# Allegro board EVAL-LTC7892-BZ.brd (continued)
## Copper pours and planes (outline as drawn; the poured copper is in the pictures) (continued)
UNNAMED_2_ADLTC7892V2_I690_SW2 on LAYER_2: 64.52,49.78 64.39,49.78 64.39,49.4 60.83,49.4 59.56,50.67 59.56,55.88 57.66,55.88 57.66,49.66 59.82,47.5 64.31,47.5 64.31,46.94 64.52,46.94 ; 1 cut-out
UNNAMED_2_ADLTC7892V2_I690_SW2 on LAYER_3: 68.58,47.02 73.15,47.02 73.15,35.05 77.22,30.99 81.28,30.99 81.28,45.97 76.07,51.18 68.58,51.18
UNNAMED_2_ADLTC7892V2_I690_SW2 on LAYER_4: 69.22,46.91 73.28,46.91 73.28,34.92 77.22,30.99 81.28,30.99 81.28,46.35 76.2,51.43 69.22,51.43
UNNAMED_2_ADLTC7892V2_I690_TGDN1 on TOP (solid shape): 62.36,69.85 61.21,69.85 59.05,67.69 59.05,63.75 58.17,62.86 58.17,64.52 58.42,64.77 58.42,67.94 61.09,70.61 62.36,70.61
UNNAMED_2_ADLTC7892V2_I690_TGDN2 on TOP (solid shape): 58.47,55.09 58.47,54.18 59.56,53.09 59.56,50.67 60.83,49.4 62.48,49.4 62.48,48.64 60.45,48.64 58.86,50.23 58.86,52.64 58.17,53.34 58.17,55.24 58.32,55.24
UNNAMED_2_ADLTC7892V2_I690_TGUP1 on TOP (solid shape): 62.36,70.99 61.09,70.99 58.17,68.07 58.17,65.02 57.91,64.77 57.91,63.5 57.78,63.5 57.53,63.75 57.53,68.45 60.83,71.75 62.36,71.75
UNNAMED_2_ADLTC7892V2_I690_TGUP2 on TOP (solid shape): 58.42,52.45 58.42,50.04 60.2,48.26 62.48,48.26 62.48,47.5 59.82,47.5 57.66,49.66 57.66,53.21
UNNAMED_2_CAP_I211_N1 on BOTTOM: 54.48,69.22 54.48,64.9 55.88,64.9 55.88,69.22
UNNAMED_2_CAP_I552_N1 on TOP: 56.13,51.64 56.13,49.35 57.28,49.35 57.28,51.64
UNNAMED_2_CAP_I715_N1 on BOTTOM: 49.34,64.52 49.34,63.5 51.75,63.5 51.75,64.52
UNNAMED_2_CAP_I718_N1 on BOTTOM: 12.95,51.05 12.95,44.83 14.22,44.83 14.22,51.05
UNNAMED_2_CAP_I719_N1 on BOTTOM: 12.95,25.02 12.95,19.18 14.22,19.18 14.22,25.02
UNNAMED_2_CNBNC5P_I602_CNTR on TOP: 62.74,71.75 62.74,69.85 63.5,69.85 63.5,70.99 64.77,70.99 64.77,71.75
UNNAMED_2_CNBNC5P_I602_CNTR on BOTTOM: 62.74,72.01 62.74,70.99 64.77,70.99 64.77,72.01
UNNAMED_2_CNBNC5P_I603_CNTR on TOP: 62.74,49.4 64.64,49.4 64.64,48.64 63.83,48.64 63.5,48.31 63.5,47.5 62.74,47.5
UNNAMED_2_CNBNC5P_I603_CNTR on BOTTOM: 62.74,48.56 64.77,48.56 64.77,49.45 62.74,49.45
UNNAMED_2_IND_I545_N2 on BOTTOM: 62.74,83.19 66.67,83.19 66.67,91.57 61.98,96.27 54.1,96.27 54.1,89.41 61.59,89.41 62.74,88.27
UNNAMED_2_IND_I546_N1 on BOTTOM: 62.48,35.94 62.48,31.24 61.21,29.97 54.36,29.97 54.36,23.37 64.14,23.37 66.8,26.03 66.8,35.94
UNNAMED_2_RES_I628_N1 on TOP: 62.74,67.94 62.74,65.91 64.06,65.91 64.06,67.18 64.67,67.18 64.67,67.94
UNNAMED_2_RES_I641_N2 on TOP: 62.74,53.21 64.64,53.21 64.64,52.45 63.94,52.45 63.94,51.43 62.74,51.43
VFB1 on TOP: 54.48,70.74 54.48,65.02 55.75,65.02 55.75,70.74
VFB2 on TOP: 52.98,53.31 52.98,47.75 55.63,47.75 55.63,49 54.36,49 54.05,49.3 54.05,53.31
VOSP1 on TOP: 56.39,73.15 56.39,68.2 57.45,68.2 57.45,73.15
VOSP2 on TOP: 51.28,50.55 51.28,46.41 52.3,46.41 52.3,50.55
VOUT1 on TOP: 102.74,81.03 114.94,81.03 119.51,76.45 119.51,59.82 102.74,59.82
VOUT1 on TOP: 58.29,74.8 58.29,72.52 59.82,72.52 60.33,72.01 64.92,72.01 64.92,70.99 67.16,70.99 67.16,72.14 80.14,72.14 80.14,68.33 103.76,68.33 103.76,81.03 76.71,81.03 74.17,78.49 64.64,78.49 64.64,74.8
VOUT1 on BOTTOM: 101.6,81.79 111.12,81.79 116.71,76.2 116.71,59.82 101.6,59.82
VOUT1 on BOTTOM: 60.71,74.55 60.71,72.39 80.14,72.39 80.14,68.33 102.36,68.33 102.36,81.79 99.69,81.79 96.39,78.49 64.52,78.49 64.52,74.55
VOUT2 on TOP: 119.51,59.31 119.51,42.42 115.44,38.35 102.74,38.35 102.74,59.31
VOUT2 on TOP: 60.58,47.24 60.58,44.58 64.52,44.58 64.52,40.89 73.66,40.89 76.2,38.35 103.76,38.35 103.76,51.05 80.14,51.05 80.14,47.24 67.18,47.24 67.18,48.39 64.9,48.39 64.9,47.24
VOUT2 on BOTTOM: 60.58,47.24 60.58,44.58 64.52,44.58 64.52,40.89 95.89,40.89 99.31,37.46 102.23,37.46 102.23,51.05 80.14,51.05 80.14,47.24
VOUT2 on BOTTOM: 116.71,59.31 116.71,43.56 110.62,37.46 101.6,37.46 101.6,59.31

Small or netless copper shapes (teardrops, artwork), in the pictures only: 7 on BOTTOM, 4 on TOP

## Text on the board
User.Comments: 1 | 5.   INSTALL BANANA JACK  KEYSTONE 575-4 AS SHOWN BELOW. | 6.    INSTALL STUD HARDWARE SET AS SHOWN BELOW: | BOTTOME SIDE | TOP SIDE | * RING LUG FACE TO THE EDGE OF THE BOARD. | SOLDER | PCB | * | NUT,BRASS,#10-32 | (PRESS FIT AND SOLDER THIS SIDE) | STUD, PRESS FIT | WASHER, LOCK #10 | LUG, RING, #10
Ref Des/Assembly Top: P3, P4.  INSTALL SHUNTS ACROSS PIN1 AND PIN2 | P1.  INSTALL SHUNT ACROSS PIN5 AND PIN6 | P2.  INSTALL SHUNT ACROSS PIN3 AND PIN4
Ref Des/Silkscreen Top: * | mm | 10 | PLLIN/SPREAD | MODE | RUN1 | RUN2 | FC MODE | PULSE SKIP | BURST MODE | ENABLE SSFM | EXTERNAL SYNC | DISABLE SSFM | FOR MAXIMUM POWER | SEE USER GUIDE | 1.2kW Max | ON | OFF | SYNC | PGOOD1 | SS1 | SS2 | VIN | PGOOD2 | DUAL OUTPUT, 2-PHASE, 100V BOOST | CONTROLLER FOR GaN FETS | EXTVCC | GND | VOSP2 | VOSP1 | 9V-36V | EVAL-LTC7892-BZ | VOUT1 | VOUT2 | 48V
PAGE_OUTLINE: INITIAL RELEASE | EVAL-LTC7892-BZ
User.9: 08-      -07 | L2-GND PLANE
User.10: 08-      -08 | L3-SIGNAL/GND
User.11: 08-      -09 | L4-SIGNAL/GND
User.12: L5-SIGNAL/GND | 08-      -10
User.19: EVAL-LTC7892-BZ  REV2 | PASTEMASK PRIMARY | NOTES: | 3. LABEL STENCIL AS SHOWN. | 1. LASER CUT STENCIL AS SHOWN. | 2. MICRO POLISH STENCIL AFTER LASER CUT.
User.20: EVAL-LTC7892-BZ REV2 | PASTEMASK SECONDARY | NOTES: | 3. LABEL STENCIL AS SHOWN. | 1. LASER CUT STENCIL AS SHOWN. | 2. MICRO POLISH STENCIL AFTER LASER CUT.
User.21: IN | OUT | SUPPLY | POWER | I | A | - | V | PGOOD2 | LOAD | +
User.32: FIGURE | SIZE | 6.0 | 9.99 | 40.0 | 100.0 | 191.0 | 213.0 | 118.0 | 185.0 | PLATED | NON-PLATED | DRILL CHART: TOP to BOTTOM | ALL UNITS ARE IN MILS | QTY | 66 | 549 | 18 | 15 | 2 | 4 | 662 | TOLERANCE/NOTES | TOTAL HOLES:
User.33: FAB NOTES REVISION: 2ND NOVEMBER 2022 | THKNS AS REQ'D | 8.   IMPEDANCE REQUIREMENTS: IF NO STACKUP IS DEFINED, THE VENDOR IS ALLOWED TO ADJUST THE DIELECTRIC | 13.  PLATING SPECIFICATION: | 1.   DIMENSIONS ARE IN INCHES (EXCEPT WHERE NOTED). | ALL DOCUMENTS & SPECIFICATIONS REFERRED TO BELOW SHOULD BE THE LATEST REVISIONS. | 2.  BOARD MATERIAL:(USE CHECKED ITEMS) | 3.   ALL LAMINATES & BONDING MATERIALS SHOULD BE SELECTED FROM IPC-4101 OR IPC-4103,(TG>170 DEGC TD>300 DEGC) | 4.   REFER TO IPC-6010 SERIES, CLASS 2 FOR FABRICATION. | 5.   REFER TO LAMINATION DIAGRAM FOR OVERALL BOARD THICKNESS, TOLERANCE APPLIES AFTER ALL LAMINATION AND PLATING | 6.   BOW & TWIST NOT TO EXCEED 0.0075 INCHES (0.75%) PER LINEAR INCH AND SHOULD BE MEASURED PER IPC-TM-650, METHOD 2.4.22. | 7.   ACCEPTABILITY PER ADI SPECIFICATION TST00115. | 9.   FILLET OPTIONS TO ENHANCE RELIABILITY AT PAD JUNCTIONS WHERE SPACING PERMITS. | 10.  THIEVING: | 11.  LAYER TO LAYER REGISTRATION SHALL BE WITHIN 0.003 INCHES. | 12.  DRILL SIZES ARE FINISHED HOLE SIZES. ALL HOLES SHALL BE LOCATED WITHIN 0.005 INCHES DTP,UNLESS SPECIFIED. | 14.  SURFACE FINISH: | 15.  SOLDERMASK: | 16.  APPLY SILKSCREEN TO BOTH SIDES USING A NON-CONDUCTIVE, EPOXY BASED INK PER ARTWORK. | (X) WHITE | ( ) OTHER | PROCESSES. FINISHED THICKNESS MEASURED FROM TOP COPPER TO BOTTOM COPPER. | (X)  ISOLA 370HR OR S1000-2 OR IT180 OR EQUIVALENT | ( )  ISOLA-FR408HR OR EQUIVALENT | ( )  ISOLA IS410 | ( )  MEGTRON 6 | ( )  NELCO-4000-13 | ( )  ROGERS 4350B | ( ) ROGERS 3003 | ( ) ARLON 85N | ( ) EM370D | ( )  OTHER ________________________ | ( ) FILLETS ALLOWED | (X) FILLETS NOT ALLOWED | ( ) VENDOR MAY ADD THIEVING TO COMPENSATE FOR LOW COPPER DENSITY AREAS MAINTAINING A MINIMUM | ( ) VENDOR MAY NOT ADD THIEVING TO COMPENSATE FOR LOW COPPER DENSITY AREAS. | (X) LPI | ( ) OTHER_________ | COLOR | (X) GREEN | HINDER PROPER SOLDER WICKING. BARREL RELIEF ON SOLDERMASK ALLOWED IN UNFILLED VIA IN PAD HOLES. | (X) REFER TO LAMINATION DIAGRAM FOR FINISHED COPPER WEIGHT/THICKNESS REQUIRMENTS | (X) IMMERSION GOLD (ENIG) 1.58-3.94 MICRO INCHES OVER 118-236 MICRO INCHES MIN. OF ELECTROLESS NICKEL PER IPC-4552 | ( ) OSP (ORGANIC SOLDERABILITY PRESERVATIVE) | ( ) IMMERSION SILVER | ( ) SOFT WIRE BONDABLE GOLD 30-50 MICRO INCHES OF SOFT WIRE | ( ) EDGE CONNECTOR FINGERS ARE TO BE PLATED WITH 100 MICRO-INCHES(.0001") OF LOW STRESS | THICKNESS & TRACE WIDTHS TO MEET THE IMPEDANCE REQUIREMENT. IF SPECIFIED, THE VENDOR MUST | TRACE WIDTH & SPACING THAT IMPACT THE REQUIREMENTS MUST HAVE WRITTEN APPROVAL FROM ADI. | MINIMUM BARREL PLATING OF 0.001 INCHES. PLATED HOLES SHALL NOT BE ROUGH OR IRREGULAR SO AS TO | SOLDERMASK OVER BARE COPPER OR BARE GOLD (BOTH SIDES) TO MEET IPC-SM-840. | IF PRESENT,DO NOT MODIFY SOLDERMASK DEFINED PADS (MASK OPENINGS LESS THAN COPPER PAD) WITHOUT APPROVAL. | MEET THE REQUIREMENTS LISTED IN THE IMPEDANCE TABLE. ANY ADJUSTMENT MADE TO THE DEFINED STACKUP, | UL FLAMMABILITY RATING 94V-0. BOARD MATERIAL & CONSTRUCTION SHALL MEET THE REQUIREMENTS OF UL796/UL796F. | BONDABLE GOLD OVER 100-150 MICRO INCHES OF NICKEL | NICKEL UNDER 30 MICRO-INCHES (.0003') OF GOLD | 0.100 INCH CLEARANCE FROM ALL COPPER FEATURES, | THE STARTING COPPER WEIGHT/THICKNESS CAN VARY AS LONG AS THE FINISHED COPPER | WEIGHT/THICKNESS IS NOT LESS THAN THE SPECIFIED VALUE. | UNLESS OTHERWISE SPECIFIED | HOMOGENOUS MATERIALS IN THIS BOARD SHALL BE COMPLAINT WITH THE EU DIRECTIVE 2002/95/EC | WORKMANSHIP SHALL CONFORM TO IPC-A-600, CLASS 2. | 21.  INTENTIONAL SHORTS: | 17.  FINAL ELECTRICAL TEST TO BE PERFORMED USING PROVIDED IPC-D-356A NETLIST OR ODB++ FORMAT FILE. | 22.  PEMNUTS: | 23.  MANUFACTURER TO ETCH/STAMP WITH PERMANENT NON-CONDUCTIVE INK | ON SECONDARY SIDE UNLESS OTHERWISE SPECIFIED: | 18.  A TIME DOMAIN REFLECTOMETER REPORT (TDR) FOR EACH IMPEDANCE CONTROLLED LAYER & A CERTIFICATE | 19.  IF PRESENT, ALL BLIND/BURIED VIAS WITH AN ASPECT RATIO <1:1 TO BE PLATED SHUT WITH COPPER WHEN | 20.  FOR VIA FILL INFORMATION REFER TO DRILL CHART: | 25. PANELIZATION: | 27.  MINIMUM DESIGN LINE WIDTH IS .008 INCH. | 28.  MINIMUM DESIGN LINE SPACING IS .006 INCH. | IS ACCEPTABLE, ALL OTHER INSTANCES MUST BE REPORTED. | IF AN INTENTIONAL SHORT REPORT IS SUPPLIED AND DOES NOT MATCH THE FAB DATA THEN | THE PCB SHALL HAVE A VERIFICATION STAMP. | (X)  NON-CONDUCTIVE EPOXY FILL ALL LESS THAN 0.010 INCHES DRILLED VIAS | ( )  COPPER FILL ALL 0.XXXX INCHES DRILLED VIAS | ( ) PEMNUTS TO BE INSTALLED BY FABRICATOR | ( ) PEMNUTS NOT TO BE INSTALLED BY FABRICATOR | ( ) NOT APPLICABLE | USED AS VIA-IN-PAD OR AS A STACKED VIA. BLIND/BURIED VIAS WITH AN ASPECT RATIO >1:1 TO BE FILLED | A. UL CODE-FLAMMABILITY RATING FOR THOSE APPROVED MATERIALS(IF APPLICABLE) | B. DATE CODE | C. LOT NUMBER | D. MANUFACTURER LOGO | BOARDS TO BE SHIPPED IN ARRAY AND KEPT INTACT | PANEL TO BE SUBJECTED TO CUSTOMERS APPROVAL | PANEL SOLDER PASTE STENCIL GERBER TO BE PROVIDED TO ANALOG | CAN'T BE PERFORMED BECAUSE THE TRACE LENGTH IS TOO SHORT ON THE OUTER LAYERS AT THE PIN ESCAPES | ADI APPROVAL IS REQUIRED. | OF COMPLIANCE SHALL BE PROVIDED BY VENDOR AT TIME OF SHIPMENT. INSTANCES WHERE TDR TESTING | WITH NON-CONDUCTIVE EPOXY. | X | 2 | NOTES: | TOOLING: | FINISH: | MATERIAL: | TESTING: | MISCELLANEOUS:
